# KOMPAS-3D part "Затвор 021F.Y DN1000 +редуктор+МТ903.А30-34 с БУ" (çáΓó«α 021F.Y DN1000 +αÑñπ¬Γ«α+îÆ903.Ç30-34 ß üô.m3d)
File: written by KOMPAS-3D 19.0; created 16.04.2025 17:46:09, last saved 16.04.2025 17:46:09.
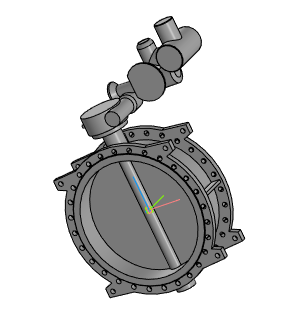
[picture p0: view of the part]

Document properties: Полное имя файла: Затвор 021F.Y DN1000 +редуктор+МТ903.А30-34 с БУ.a3d

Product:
- Part/product: Затвор 021F.Y DN1000 +редуктор+МТ903.А30-34 с БУ
    Масса: 1325.49

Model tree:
1. Операция без истории:1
